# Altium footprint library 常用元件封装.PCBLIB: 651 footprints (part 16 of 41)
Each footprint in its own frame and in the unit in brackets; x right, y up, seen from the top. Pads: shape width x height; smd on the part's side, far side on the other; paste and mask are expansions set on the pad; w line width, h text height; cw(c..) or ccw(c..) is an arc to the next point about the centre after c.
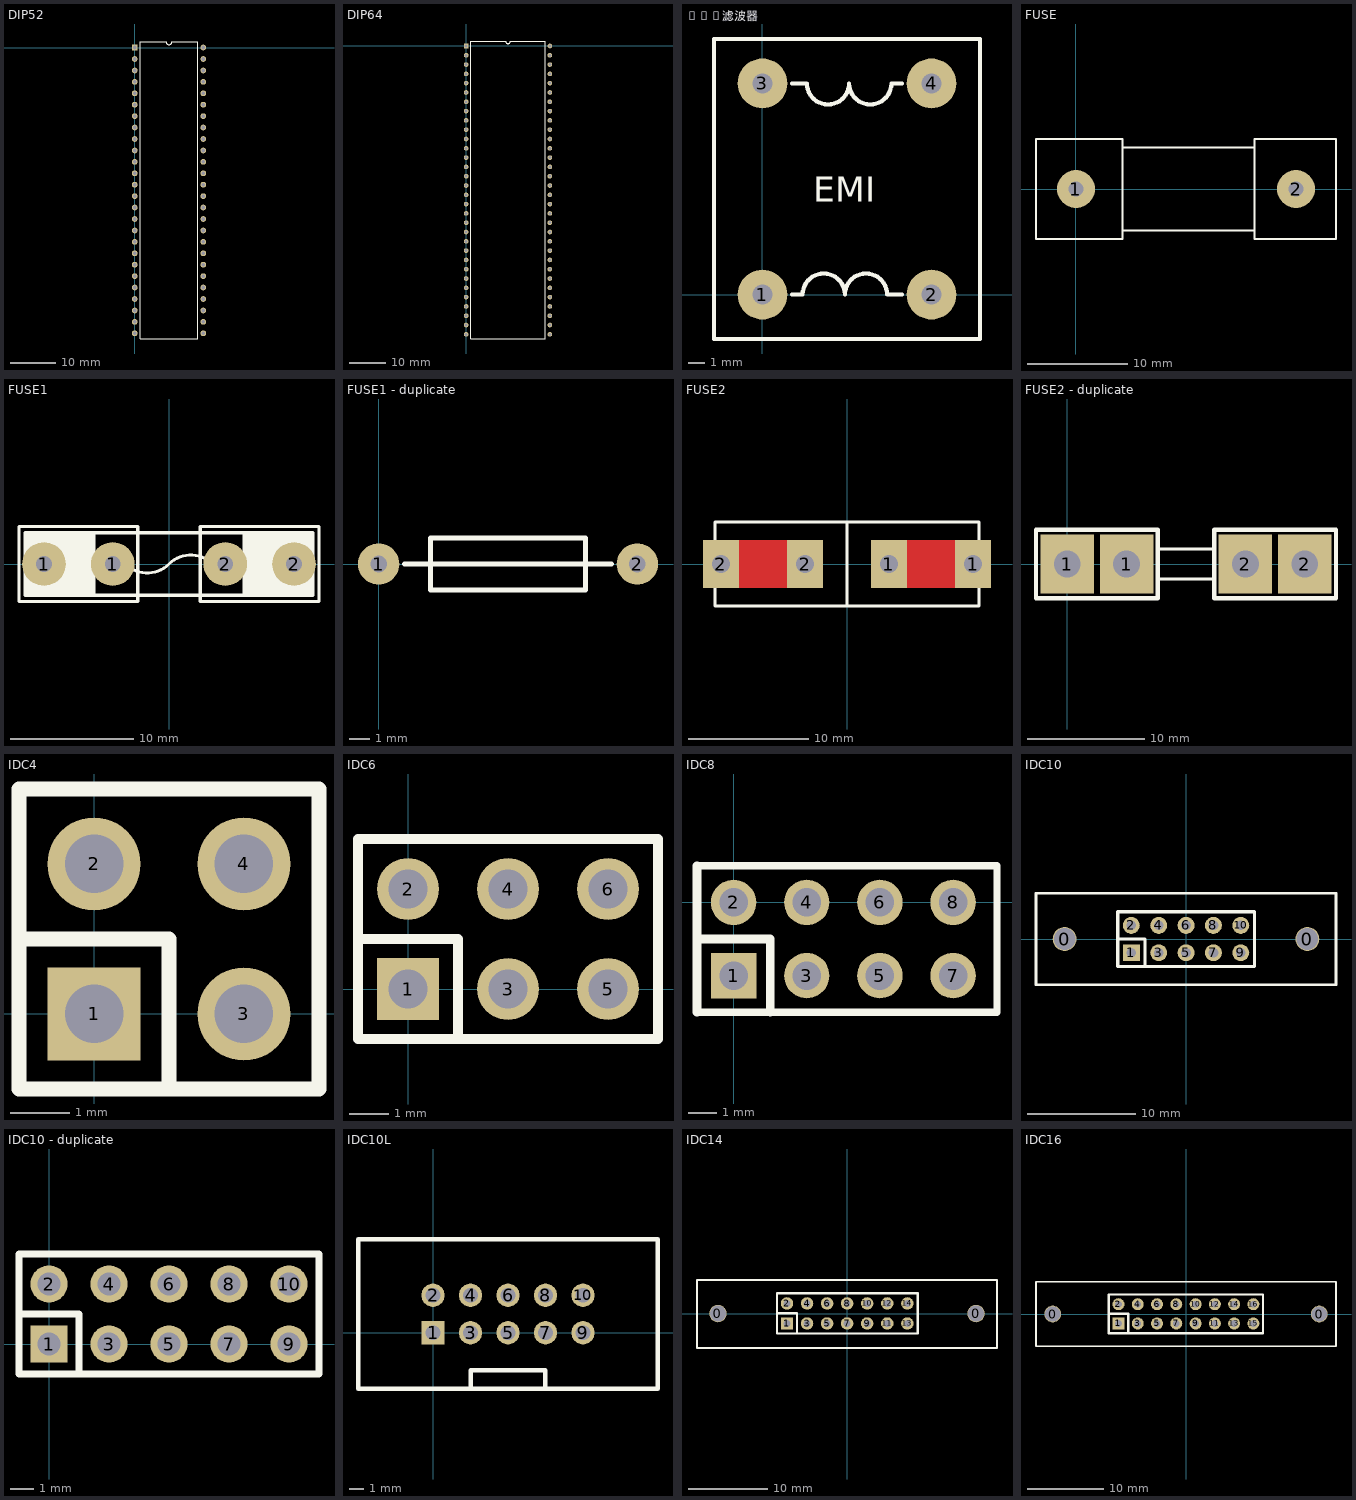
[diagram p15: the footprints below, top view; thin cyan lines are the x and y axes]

## DIP52 [mil]
pads (52):
  rect 50x50 hole 32: 1(0,0)
  round 50 hole 32: 2(0,-100) 3(0,-200) 4(0,-300) 5(0,-400) 6(0,-500) 7(0,-600) 8(0,-700) 9(0,-800) 10(0,-900) 11(0,-1000) 12(0,-1100) 13(0,-1200) 14(0,-1300) 15(0,-1400) 16(0,-1500) 17(0,-1600) 18(0,-1700) 19(0,-1800) 20(0,-1900) 21(0,-2000) 22(0,-2100) 23(0,-2200) 24(0,-2300) 25(0,-2400) 26(0,-2500) 27(600,-2500) 28(600,-2400) 29(600,-2300) 30(600,-2200) 31(600,-2100) 32(600,-2000) 33(600,-1900) 34(600,-1800) 35(600,-1700) 36(600,-1600) 37(600,-1500) 38(600,-1400) 39(600,-1300) 40(600,-1200) 41(600,-1100) 42(600,-1000) 43(600,-900) 44(600,-800) 45(600,-700) 46(600,-600) 47(600,-500) 48(600,-400) 49(600,-300) 50(600,-200) 51(600,-100) 52(600,0)
TopOverlay:
  lines w10: 50,-2550 50,50 275,50 ccw(c300,50) 325,50 550,50 550,-2550 50,-2550

## DIP64 [mil]
pads (64):
  rect 50x50 hole 32: 1(0,0)
  round 50 hole 32: 2(0,-100) 3(0,-200) 4(0,-300) 5(0,-400) 6(0,-500) 7(0,-600) 8(0,-700) 9(0,-800) 10(0,-900) 11(0,-1000) 12(0,-1100) 13(0,-1200) 14(0,-1300) 15(0,-1400) 16(0,-1500) 17(0,-1600) 18(0,-1700) 19(0,-1800) 20(0,-1900) 21(0,-2000) 22(0,-2100) 23(0,-2200) 24(0,-2300) 25(0,-2400) 26(0,-2500) 27(0,-2600) 28(0,-2700) 29(0,-2800) 30(0,-2900) 31(0,-3000) 32(0,-3100) 33(900,-3100) 34(900,-3000) 35(900,-2900) 36(900,-2800) 37(900,-2700) 38(900,-2600) 39(900,-2500) 40(900,-2400) 41(900,-2300) 42(900,-2200) 43(900,-2100) 44(900,-2000) 45(900,-1900) 46(900,-1800) 47(900,-1700) 48(900,-1600) 49(900,-1500) 50(900,-1400) 51(900,-1300) 52(900,-1200) 53(900,-1100) 54(900,-1000) 55(900,-900) 56(900,-800) 57(900,-700) 58(900,-600) 59(900,-500) 60(900,-400) 61(900,-300) 62(900,-200) 63(900,-100) 64(900,0)
TopOverlay:
  lines w10: 50,-3150 850,-3150 850,50 475,50 cw(c450,50) 425,50 50,50 50,-3150

## EMI滤波器 [mm] "18mmX16mm"
height 18
pads (4):
  round 3 hole 1.2: 1(0,0) 2(10.16,0) 3(0,12.7) 4(10.16,12.7)
TopOverlay:
  lines w0.254: 1.778,0 2.413,0 cw(c3.683,0) 3.683,1.27 cw(c3.683,0) 4.953,0 cw(c6.223,0) 6.223,1.27 cw(c6.223,0) 7.493,0 8.382,0 ; 1.778,12.7 2.667,12.7 ccw(c3.937,12.7) 3.937,11.43 ccw(c3.937,12.7) 5.207,12.7 ccw(c6.477,12.7) 6.477,11.43 ccw(c6.477,12.7) 7.747,12.7 8.382,12.7 ; -2.921,-2.667 -2.921,15.367 13.081,15.367 13.081,-2.667 -2.921,-2.667
  text "EMI" at 3.048,5.588 h1.52

## FUSE [mm]
pads (2):
  round 3.81 hole 1.5: 1(0,0) 2(22,0)
TopOverlay:
  lines w0.203: 4.636,-4.136 17.844,-4.136 ; 4.636,4.136 17.844,4.136 ; -4,-5 4.636,-5 4.636,5 -4,5 -4,-5 ; 17.844,-5 26,-5 26,5 17.844,5 17.844,-5

## FUSE1 [mil]
pads (4):
  round 140 hole 50: 1(-400,0) 1(-180,0) 2(180,0) 2(400,0)
TopOverlay:
  rectangle: -460,-100 -240,100
  rectangle: 240,-100 460,100
  lines w10: -240,-100 -240,100 ; -140,0 ccw(c-70,70) 0,0 cw(c70,-70) 140,0 ; 240,-100 240,100 ; -480,-120 -480,0 -480,120 -100,120 -100,-120 -480,-120 ; -460,-100 460,-100 460,100 440,100 -460,100 -460,-100 ; 100,-120 100,120 480,120 480,-120 100,-120

## FUSE1 - duplicate [mil] "12.7mm"
height 236.22
pads (2):
  round 80 hole 32: 1(0,0) 2(500,0)
TopOverlay:
  lines w10: 50,0 450,0 ; 100,-50 100,50 400,50 400,-50 100,-50

## FUSE2 [mil]
pads (4):
  rect 118x157 hole 59: 1(137.5,0) 1(413.5,0) 2(-413.5,0) 2(-137.5,0)
TopLayer:
  rectangle: 177.5,-79 374.5,79
  rectangle: -373.5,-79 -177.5,79
BottomLayer:
  rectangle: -373.5,-79 -177.5,79
  rectangle: 177.5,-79 374.5,79
TopOverlay:
  lines w10: 0.5,-138 0.5,138 ; -432.5,-138 -432.5,138 433.5,138 433.5,-138 -432.5,-138

## FUSE2 - duplicate [mil] "铜片插座"
height 314.96
pads (4):
  rect 180x200 hole 90: 1(0,0) 1(200,0) 2(600,0) 2(800,0)
TopOverlay:
  lines w10: 305,-50 495,-50 ; 305,50 495,50
  lines w15: -105,-115 -105,115 305,115 305,-115 -105,-115 ; 495,-115 905,-115 905,115 495,115 495,-115

## IDC4 [mil]
pads (4):
  rect 62x62 hole 39: 1(0,0)
  round 62 hole 39: 2(0,100) 3(100,0) 4(100,100)
TopOverlay:
  lines w10: -50,50 50,50 50,-50 ; -50,-50 150,-50 150,150 -50,150 -50,-50

## IDC6 [mil]
pads (6):
  rect 62x62 hole 39: 1(0,0)
  round 62 hole 39: 2(0,100) 3(100,0) 4(100,100) 5(200,0) 6(200,100)
TopOverlay:
  lines w10: -50,50 50,50 50,-50 ; -50,-50 250,-50 250,150 -50,150 -50,-50

## IDC8 [mil]
pads (8):
  rect 62x62 hole 39: 1(0,-100)
  round 62 hole 39: 2(0,0) 3(100,-100) 4(100,0) 5(200,-100) 6(200,0) 7(300,-100) 8(300,0)
TopOverlay:
  lines w10: -50,-150 360,-150 360,50 -50,50
  lines w12: -50,-150 -50,50 ; -50,-50 50,-50 50,-150

## IDC10 [mm]
pads (12):
  round 2.2 hole 2: 0(-11.27,0) 0(11.27,0)
  rect 1.575x1.575 hole 0.9: 1(-5.075,-1.275)
  round 1.575 hole 0.9: 2(-5.075,1.265) 3(-2.535,-1.275) 4(-2.535,1.265) 5(0.005,-1.275) 6(0.005,1.265) 7(2.545,-1.275) 8(2.545,1.265) 9(5.085,-1.275) 10(5.085,1.265)
TopOverlay:
  lines w0.254: -13.92,-4.25 13.92,-4.25 13.92,4.25 -13.92,4.25 -13.92,-4.25
  lines w0.305: -6.345,-0.005 -3.805,-0.005 -3.805,-2.545 ; -6.345,-2.545 -6.345,2.535 6.355,2.535 6.355,-2.545 -6.345,-2.545

## IDC10 - duplicate [mil]
pads (10):
  rect 62x62 hole 39: 1(0,0)
  round 62 hole 39: 2(0,100) 3(100,0) 4(100,100) 5(200,0) 6(200,100) 7(300,0) 8(300,100) 9(400,0) 10(400,100)
TopOverlay:
  lines w12: -50,50 50,50 50,-50 ; -50,-50 -50,150 450,150 450,-50 -50,-50

## IDC10L [mil]
pads (10):
  rect 62x62 hole 39: 1(0,0)
  round 62 hole 39: 2(0,100) 3(100,0) 4(100,100) 5(200,0) 6(200,100) 7(300,0) 8(300,100) 9(400,0) 10(400,100)
TopOverlay:
  lines w12: 100,-150 100,-100 300,-100 300,-150 ; -200,-150 -200,250 600,250 600,-150 -200,-150

## IDC14 [mm]
pads (16):
  round 2.2 hole 2: 0(-16.35,0) 0(16.35,0)
  rect 1.575x1.575 hole 0.9: 1(-7.601,-1.25)
  round 1.575 hole 0.9: 2(-7.601,1.29) 3(-5.061,-1.25) 4(-5.061,1.29) 5(-2.521,-1.25) 6(-2.521,1.29) 7(0.019,-1.25) 8(0.019,1.29) 9(2.559,-1.25) 10(2.559,1.29) 11(5.099,-1.25) 12(5.099,1.29) 13(7.639,-1.25) 14(7.639,1.29)
TopOverlay:
  lines w0.254: -19,-4.35 19,-4.35 19,4.25 -19,4.25 -19,-4.35
  lines w0.305: -8.871,0.02 -6.331,0.02 -6.331,-2.52 ; 8.979,-2.52 8.979,2.56 ; 8.983,-2.515 -8.871,-2.52 -8.871,2.56 8.983,2.57

## IDC16 [mm]
pads (18):
  round 2.2 hole 2: 0(-17.57,0) 0(17.57,0)
  rect 1.575x1.575 hole 0.9: 1(-8.9,-1.25)
  round 1.575 hole 0.9: 2(-8.9,1.29) 3(-6.36,-1.25) 4(-6.36,1.29) 5(-3.82,-1.25) 6(-3.82,1.29) 7(-1.28,-1.25) 8(-1.28,1.29) 9(1.26,-1.25) 10(1.26,1.29) 11(3.8,-1.25) 12(3.8,1.29) 13(6.34,-1.25) 14(6.34,1.29) 15(8.88,-1.25) 16(8.88,1.29)
TopOverlay:
  lines w0.254: 19.765,-4.25 19.765,4.25 ; 19.77,-4.25 -19.77,-4.25 -19.77,4.25 19.77,4.25
  lines w0.305: -10.17,0.02 -7.63,0.02 -7.63,-2.52 ; -10.17,-2.52 10.15,-2.52 10.15,2.56 -10.17,2.56 -10.17,-2.52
